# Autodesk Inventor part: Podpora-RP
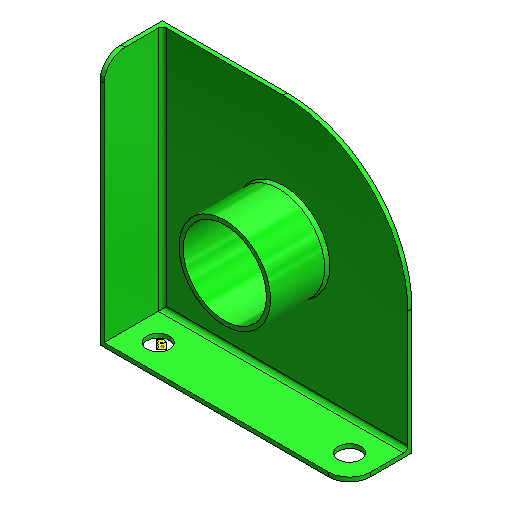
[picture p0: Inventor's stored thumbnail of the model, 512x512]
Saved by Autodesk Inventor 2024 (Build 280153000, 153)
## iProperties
Company: ATC
Shininess: 0.0
Length Units: 11269
Angle Units: 11279
Time Units: 11290
Mass Units: 11283
Length Display Precision: 3
Angle Display Precision: 2
Compacted: True
Created: 2023-03
Part Number: Podpora-RP
Document SubType Name: Modeling
Designer: Andrzej Jaskulski
Material: Stal węglowa
Density: 7.87 g/cm^3
Stock Number: Podpora-RP
Mass: 3651.54 g
Surface Area: 1854.71 cm^2
Volume: 365.154 cm^3
Appearance: Stal
Checked By: A.J.
Engr Approved By: Andrzej Jaskulski
Mfg Approved By: Andrzej Jaskulski
Authority: A.J.
Density: 0.0
Volumn: 0.0
Area: 0.0
PropertySet Name: Model Information
Control State: 0
Master: False
Checked Out: False
Title: A.J.: Kurs R2024-MEP
Author: Andrzej Jaskulski
Revision Number: 1/24
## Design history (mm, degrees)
node "Extrusion1" dims "d1" = 60, "d2" = 0
  sketch "Sketch1"
    geometry: L1 (0, 0)-(240, 0); L2 (240, 0)-(240, 240); L3 (240, 240)-(0, 240); L4 (0, 240)-(0, 0)
    constraints: 8 end point, 2 parallel, 2 perpendicular, 1 horizontal, 1 other
    dimensions: "d0" = 240 distance of L1.start L1.end
node "Hole1" dims "d5" = 80, "d6" = 4, "d7" = 2, "d8" = 60 deg, "d9" = 8, "d10" = 118 deg, "d37" = 6
  sketch "Sketch3"
    geometry: L1 (0, 0)-(240, 0) reference; L2 (0, 240)-(0, 0) reference; 1 further point
    dimensions: "d3" = 120 distance from line of L1 point (120, 120); "d4" = 120 distance from line of L2 point (120, 120)
node "Fillet1" dims "d12" = 20
node "Fillet2" dims "d13" = 120
node "Shell2" dims "d14" = 4
node "Fillet3" dims "d30" = 4
node "Chamfer1" dims "d31" = 4, "d32" = 1, "d35" = 45 deg
node "Otwory22"
node "Otwory23"
node "Bryła1"
node "Korpusy bryłowe"
node "Korpusy powierzchniowe"
node "Szkic6"
node "Szkic7"
sketch "Szkic27"
  geometry: 1 further point
hole "Otwór33" sketch "Szkic27" diameter "d248" = 22; stored, may be unused: countersink angle "d252" = 90 deg, drill point angle "d254" = 0 deg; dims "d249" = 6, "d250" = 4, "d251" = 2, "d253" = 8
sketch "Szkic28"
  geometry: 1 further point
hole "Otwór34" sketch "Szkic28" diameter "d255" = 22; stored, may be unused: countersink angle "d259" = 90 deg, drill point angle "d261" = 0 deg; dims "d256" = 6, "d257" = 4, "d258" = 2, "d260" = 8
